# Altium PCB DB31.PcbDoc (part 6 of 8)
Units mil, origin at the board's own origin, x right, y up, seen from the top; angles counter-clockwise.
Board outline 3236.22 x 4456.69 mil, 8 copper layers (Top Layer, MidLayer1, MidLayer2, GND-Layer5, MidLayer3, VCC, MidLayer4, Bottom Layer), stack 61.8 mil thick; 226 components, 469 nets, 1815 pads, 1562 vias.
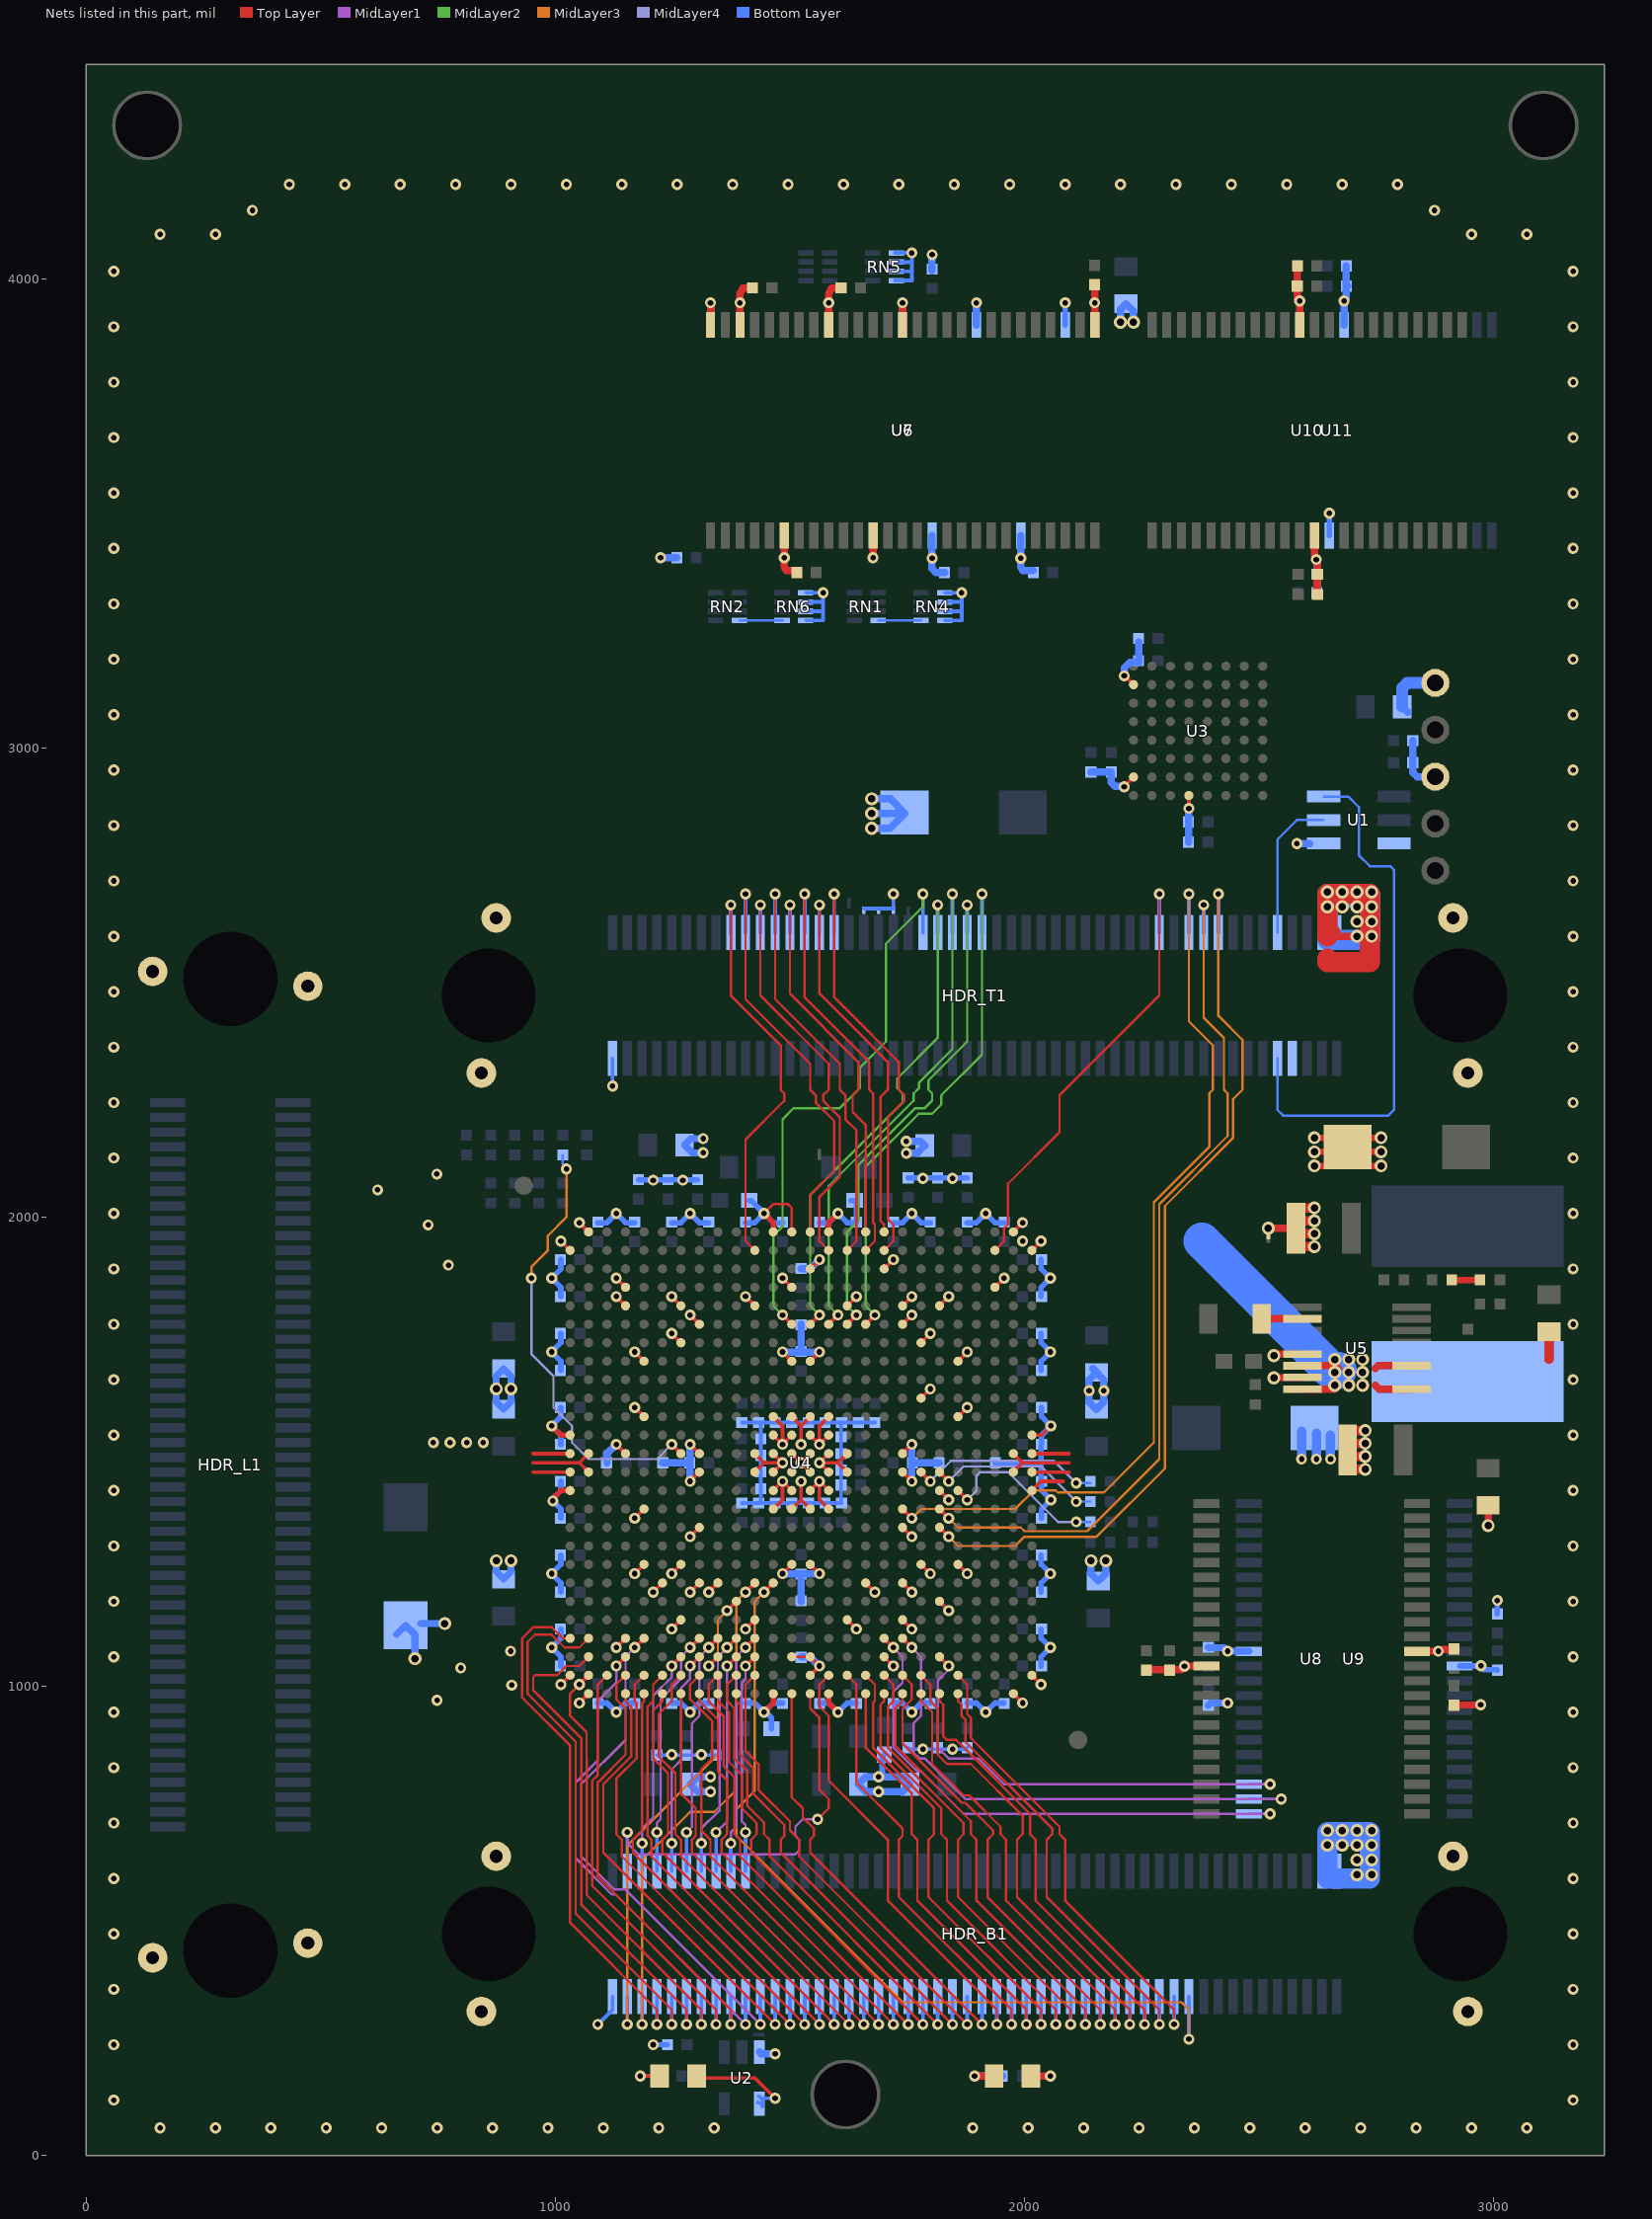
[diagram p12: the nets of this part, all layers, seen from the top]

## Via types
v1: diameter 23.62, hole 11.81, Top Layer to Bottom Layer, 947 vias
v2: diameter 23.62, hole 11.81, Top Layer to Bottom Layer, tented both sides, 476 vias
v3: diameter 27.56, hole 15.75, Top Layer to Bottom Layer, 138 vias
v4: diameter 23.62, hole 11.81, Top Layer to Bottom Layer, tented top, 1 vias

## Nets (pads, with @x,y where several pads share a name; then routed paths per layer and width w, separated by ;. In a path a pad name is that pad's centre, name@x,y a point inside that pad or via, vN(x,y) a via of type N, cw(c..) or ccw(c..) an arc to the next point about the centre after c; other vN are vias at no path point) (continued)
GND: C1.1 C2.2 C3.2 C4.2 C5.2 C6.2 C7.2 C8.2 C9.2 C10.2 C11.2 C12.2 C13.2 C14.2 C15.2 C16.2 C17.2 C18.2 C19.2 C20.2 C21.2 C22.2 C23.2 C24.2 C25.2 C26.2 C27.2 C28.2 C29.2 C30.2 C31.2 C32.2 C33.2 C34.2 C35.2 C36.2 C37.2 C38.2 C39.2 C40.2 C41.2 C42.2 C43.2 C44.2 C45.2 C46.2 C47.2 C48.2 C49.2 C50.2 C51.2 C52.2 C53.2 C54.2 C55.2 C56.2 C57.2 C58.2 C59.2 C60.2 C61.2 C62.2 C63.2 C64.2 C65.2 C66.2 C67.2 C68.2 C69.2 C70.2 C71.2 C72.2 C73.2 C74.2 C75.2 C76.2 C77.2 C78.2 C79.2 C80.2 C81.2 C82.2 C83.2 C84.2 C85.2 C86.2 C87.2 C88.2 C89.2 C90.2 C91.2 C92.2 C93.2 C94.2 C95.2 C96.2 C97.2 C98.2 C99.2 C100.2 C101.1 C102.2 C103.2 C104.2 C105.2 C106.2 C107.2 C108.2 C109.2 C110.2 C111.2 C112.2 C113.2 C114.2 C115.2 C116.2 C117.2 C118.2 C119.2 C120.2 C121.2 C122.2 C123.2 C124.2 C125.2 C128.2 C129.2 C130.2 C131.2 C132.2 C134.2 C135.2 C136.2 C137.2 C138.2 C139.2 C140.2 C141.2 C142.2 C143.2 C144.2 C145.2 C146.2 C147.2 C148.2 C149.2 C150.2 C151.2 C152.2 C153.2 C154.2 C155.2 C156.2 C157.2 HDR_B1.1 HDR_B1.98 HDR_B1.100 HDR_B1.MH1 HDR_B1.MH2 HDR_B1.MH3 HDR_B1.MH4 HDR_L1.MH1 HDR_L1.MH2 HDR_L1.MH3 HDR_L1.MH4 HDR_T1.1 HDR_T1.98 HDR_T1.100 HDR_T1.MH1 HDR_T1.MH2 HDR_T1.MH3 HDR_T1.MH4 LED2.2 NT5.2 NT6.2 NT7.2 NT8.2 RN4.1 RN4.2 RN4.3 RN4.4 RN5.1 RN5.2 RN5.3 RN5.4 RN6.1 RN6.2 RN6.3 RN6.4 TP1.1 TP3.1 U1.1 U2.3 U3.E8 U3.H2 U3.H7 U4.A2 U4.A12 U4.A13 U4.A15 U4.A25 U4.AA21 U4.AB7 U4.AB11 U4.AB16 U4.AB19 U4.AC4 U4.AD9 U4.AD13 U4.AD14 U4.AD18 U4.AE1 U4.AE14 U4.AE26 U4.AF2 U4.AF12 U4.AF15 U4.AF25 U4.B1 U4.B26 U4.C14 U4.C18 U4.D4 U4.D13 U4.D24 U4.E4 U4.E7 U4.E11 U4.E16 U4.E19 U4.E21 U4.F8 U4.F19 U4.G7 U4.G20 U4.H5 U4.H13 U4.H14 U4.H22 U4.K20 U4.L5 U4.L12 U4.L13 U4.L14 U4.L15 U4.L22 U4.M1 U4.M12 U4.M13 U4.M14 U4.M15 U4.M26 U4.N1 U4.N2 U4.N4 U4.N8 U4.N11 U4.N12 U4.N13 U4.N14 U4.N15 U4.N16 U4.N19 U4.N25 U4.N26 U4.P1 U4.P2 U4.P8 U4.P11 U4.P12 U4.P13 U4.P14 U4.P15 U4.P16 U4.P19 U4.P25 U4.P26 U4.R1 U4.R12 U4.R13 U4.R14 U4.R15 U4.R21 U4.R26 U4.T5 U4.T12 U4.T13 U4.T14 U4.T15 U4.U8 U4.U19 U4.W5 U4.W7 U4.W13 U4.W14 U4.W20 U4.W22 U4.Y6 U4.Y8 U4.Y9 U4.Y17 U4.Y19 U5.13 U5.15 U6.6 U6.12 U6.28 U6.41 U6.46 U6.52 U6.54 U7.6 U7.12 U7.28 U7.41 U7.46 U7.52 U7.54 U8.12 U8.34 U9.12 U9.34 U10.12 U10.34 U11.12 U11.34 | length 16400.1
  Top Layer w5: v1(1444.88,2007.87) 1464.57,2027.56 1496.06,2027.56 1503.94,2019.68 U4.A13@1503.94,1968.5 ; U4.AD13@1503.94,1062.99 U4.AD14@1543.31,1062.99
  Top Layer w7.87: 952.76,1456.69 U4.P1@1031.5,1456.69 ; 952.76,1476.38 1011.81,1476.38 1051.18,1476.38 ; 952.76,1496.06 U4.N1@1031.5,1496.06 ; v1(1011.81,1003.93) U4.AE1@1031.5,1023.62 ; v1(1011.81,1948.82) U4.B1@1031.5,1929.13 ; v1(1051.18,964.56) U4.AF2@1070.87,984.25 ; v1(1051.18,1988.19) U4.A2@1070.87,1968.5 ; U4.P2@1070.87,1456.69 1051.18,1476.38 ; U4.N2@1070.87,1496.06 1051.18,1476.38 ; v1(1129.92,1082.67) U4.AC4@1149.61,1102.36 ; v1(1129.92,1515.75) U4.N4@1149.61,1496.06 ; v1(1129.92,1830.71) U4.E4@1149.61,1811.02 ; v1(1129.92,1870.08) U4.D4@1149.61,1850.39 ; v1(1169.29,1240.16) U4.W5@1188.98,1259.84 ; v1(1169.29,1358.27) U4.T5@1188.98,1377.95 ; v1(1169.29,1594.49) U4.L5@1188.98,1574.8 ; v1(1169.29,1712.6) U4.H5@1188.98,1692.91 ; v1(1208.66,1200.78) U4.Y6@1228.35,1220.47 ; v1(1248.03,1122.04) U4.AB7@1267.72,1141.73 ; v1(1248.03,1240.16) U4.W7@1267.72,1259.84 ; v1(1248.03,1751.97) U4.G7@1267.72,1732.28 ; v1(1248.03,1830.71) U4.E7@1267.72,1811.02 ; v1(1287.4,1200.78) U4.Y8@1307.09,1220.47 ; v1(1287.4,1318.9) U4.U8@1307.09,1338.58 ; v1(1287.4,1437.01) U4.P8@1307.09,1456.69 ; v1(1287.4,1515.75) U4.N8@1307.09,1496.06 ; v1(1287.4,1791.34) U4.F8@1307.09,1771.65 ; v1(1326.77,1043.3) U4.AD9@1346.46,1062.99 ; v1(1326.77,1200.78) U4.Y9@1346.46,1220.47 ; v1(1405.51,1122.04) U4.AB11@1425.2,1141.73 ; v1(1405.51,1830.71) U4.E11@1425.2,1811.02 ; U4.P11@1425.2,1456.69 1444.88,1476.38 ; U4.N11@1425.2,1496.06 1444.88,1476.38 ; U4.T12@1464.57,1377.95 1484.25,1397.64 v1(1484.25,1437.01) ; U4.R12@1464.57,1417.32 v1(1484.25,1437.01) ; U4.P12@1464.57,1456.69 v1(1484.25,1476.38) ; U4.N12@1464.57,1496.06 v1(1484.25,1476.38) ; U4.M12@1464.57,1535.43 v1(1484.25,1515.75) ; U4.L12@1464.57,1574.8 1484.25,1555.12 v1(1484.25,1515.75) ; v1(1484.25,1240.15) U4.W13@1503.94,1259.84 ; v1(1484.25,1712.6) U4.H13@1503.94,1692.91 ; v1(1484.25,1870.08) U4.D13@1503.94,1850.39 ; U4.T13@1503.94,1377.95 1523.62,1397.64 ; U4.R13@1503.94,1417.32 v1(1484.25,1437.01) ; U4.P13@1503.94,1456.69 v1(1523.62,1476.38) ; U4.N13@1503.94,1496.06 v1(1523.62,1476.38) ; U4.M13@1503.94,1535.43 v1(1484.25,1515.75) ; U4.L13@1503.94,1574.8 1523.62,1555.12 ; v1(1523.62,1437.01) 1523.62,1397.64 ; v1(1523.62,1515.75) 1523.62,1555.12 ; U4.AE14@1543.31,1023.62 v1(1562.99,1043.3) U4.AD14@1543.31,1062.99 ; U4.W14@1543.31,1259.84 v1(1562.99,1240.16) ; U4.T14@1543.31,1377.95 1523.62,1397.64 ; U4.R14@1543.31,1417.32 v1(1562.99,1437.01) ; U4.P14@1543.31,1456.69 v1(1523.62,1476.38) ; U4.N14@1543.31,1496.06 v1(1523.62,1476.38) ; U4.M14@1543.31,1535.43 v1(1562.99,1515.75) ; U4.L14@1543.31,1574.8 1523.62,1555.12 ; U4.H14@1543.31,1692.91 v1(1562.99,1712.6) ; U4.C14@1543.31,1889.76 v1(1562.99,1909.45) ; U4.T15@1582.68,1377.95 1562.99,1397.64 v1(1562.99,1437.01) ; U4.R15@1582.68,1417.32 v1(1562.99,1437.01) ; U4.P15@1582.68,1456.69 v1(1562.99,1476.38) ; U4.N15@1582.68,1496.06 v1(1562.99,1476.38) ; U4.M15@1582.68,1535.43 v1(1562.99,1515.75) ; U4.L15@1582.68,1574.8 1562.99,1555.12 v1(1562.99,1515.75) ; U4.AB16@1622.05,1141.73 v1(1641.73,1122.04) ; U4.P16@1622.05,1456.69 1602.36,1476.38 ; U4.N16@1622.05,1496.06 1602.36,1476.38 ; U4.E16@1622.05,1811.02 v1(1641.73,1830.71) ; U4.Y17@1661.42,1220.47 v1(1681.1,1200.78) ; U4.AD18@1700.79,1062.99 v1(1720.47,1043.3) ; U4.C18@1700.79,1889.76 v1(1720.47,1909.45) ; U4.AB19@1740.16,1141.73 v1(1759.84,1122.04) ; U4.Y19@1740.16,1220.47 v1(1759.84,1200.78) ; U4.U19@1740.16,1338.58 v1(1759.84,1318.9) ; U4.P19@1740.16,1456.69 v1(1759.84,1437.01) ; U4.N19@1740.16,1496.06 v1(1759.84,1515.75) ; U4.F19@1740.16,1771.65 v1(1759.84,1791.34) ; U4.E19@1740.16,1811.02 v1(1759.84,1830.71) ; U4.W20@1779.53,1259.84 v1(1799.22,1240.16) ; U4.K20@1779.53,1614.17 v1(1799.22,1633.86) ; U4.G20@1779.53,1732.28 v1(1799.21,1751.97) ; U4.AA21@1818.9,1181.1 v1(1838.59,1161.41) ; U4.R21@1818.9,1417.32 v1(1838.59,1397.64) ; U4.E21@1818.9,1811.02 v1(1838.58,1830.71) ; U4.W22@1858.27,1259.84 v1(1877.96,1240.16) ; U4.L22@1858.27,1574.8 v1(1877.96,1594.49) ; U4.H22@1858.27,1692.91 v1(1877.96,1712.6) ; U4.D24@1937.01,1850.39 v1(1956.7,1870.08) ; U4.AF25@1976.38,984.25 v1(1996.07,964.57) ; U4.P25@1976.38,1456.69 1996.06,1476.38 ; U4.N25@1976.38,1496.06 1996.06,1476.38 ; U4.A25@1976.38,1968.5 v1(1996.06,1988.19) ; U4.AE26@2015.75,1023.62 v1(2035.44,1003.94) ; U4.R26@2015.75,1417.32 2035.43,1437.01 2082.68,1437.01 ; U4.P26@2015.75,1456.69 2094.49,1456.69 ; U4.N26@2015.75,1496.06 2094.49,1496.06 ; U4.M26@2015.75,1535.43 2036.42,1535.43 v1(2056.1,1555.11) ; U4.B26@2015.75,1929.13 v1(2035.43,1948.82) ; 2094.49,1476.38 1996.06,1476.38 ; v1@2212.6,2918.31 U3.H7@2232.28,2937.99 ; v1@2212.6,3154.53 U3.H2@2232.28,3134.84 ; v1(2350.4,2871.07) U3.E8@2350.39,2898.62 ; 1444.88,1476.38 v1(1484.25,1476.38) ; v1(1562.99,1476.38) 1602.36,1476.38
  Top Layer w11.81: v1@992.13,1397.64 1011.81,1417.32 U4.R1@1031.5,1417.32 ; v1(992.13,1555.12) 1011.81,1535.43 U4.M1@1031.5,1535.43 ; v1(1444.88,944.88) 1464.57,964.57 U4.AF12@1464.57,984.25 ; v1(1444.88,2007.87) 1464.57,1988.19 U4.A12@1464.57,1968.5 ; U4.AF15@1582.68,984.25 1582.68,964.57 v1(1602.36,944.88) ; U4.A15@1582.68,1968.5 1582.68,1988.19 v1(1602.36,2007.87)
  Top Layer w13.78: v3(2618.11,2109.29) C128.2@2669.08,2109.29 ; v3(2618.11,2139.29) C128.2@2669.08,2139.29 ; v3(2618.11,2169.29) C128.2@2669.08,2169.29 ; C128.2@2709.01,2109.29 v3(2759.99,2109.29) ; C128.2@2709.01,2139.29 v3(2759.99,2139.29) ; C128.2@2709.01,2169.29 v3(2759.99,2169.29)
  Top Layer w15: C145.2@2259.84,1034.45 2260.82,1035.43 2334.65,1035.43 2341,1041.79 v1(2341,1043) 2341.3,1043.3 U8.34@2387.89,1043.3 ; v3(2531.5,1657.48) 2532.26,1658.25 U5.15@2591.08,1658.25 ; v3(2531.5,1704.72) 2535.43,1708.66 U5.13@2590.55,1708.66 ; U8.12@2836.71,1074.8 2881.8,1074.8 v1(2882,1075) 2886.02,1075 2889.76,1078.74 2914.47,1078.74 C142.2@2915.44,1079.71 ; C144.2@2915.3,957.92 2917.32,957.76 2914.45,960.63 v1(2972.44,960.63)
  Top Layer w15.75: U6.54@1330.71,3901.57 v2(1330.71,3948.82) ; U6.52@1393.7,3901.57 v2(1393.7,3948.82) ; v2@1393.7,3944.88 1393.7,3964.57 ; 1393.7,3968.51 1399.61,3980.32 C138.2@1420.27,3980.31 ; C138.2@1416.34,3980.32 C138.2@1418.31,3978.34 ; U6.6@1488.19,3452.76 1488.19,3409.45 v2(1488.19,3405.51) 1488.19,3385.83 1492.13,3377.95 C135.2@1514.77,3377.95 ; U6.46@1582.68,3901.57 v2(1582.68,3948.82) ; v2@1582.68,3944.88 1582.68,3964.57 1582.68,3968.51 1588.58,3980.32 C139.2@1609.25,3980.31 ; v2(1677.17,3405.51) U6.12@1677.17,3452.76 ; U6.41@1740.16,3901.57 v2(1740.16,3948.82) ; LED2.2@2011.81,169.29 v1(2055.12,169.29) ; U6.28@2149.61,3901.57 C134.2@2149.6,3987.2 ; v3(2519.68,1976.38) C132.2@2582.67,1976.38 ; C151.2@2580.43,4028.54 C151.2@2580.57,4028.67 ; C151.2@2581.69,4027.55 2581.69,3957.68 v2(2586.61,3952.76) U10.34@2586.61,3901.57 ; U10.12@2618.11,3452.76 2618.11,3405.51 2624.72,3398.9 C154.2@2624.72,3370.07 C154.2@2625.71,3371.06 ; C150.2@2623.74,3329.72 2623.74,3370.07 C154.2@2623.77,3370.23 ; 2645.67,2598.43 v3(2708.66,2598.43) ; v3(2988.19,1342.52) C129.2@2988.18,1385.82
  Top Layer w19.68: 2645.67,2551.18 2649.61,2555.12 ; 3118.09,1696.83 C131.2@3118.1,1755.9
  Top Layer w20: C132.2@2578.73,1937 v3(2618.1,1937) ; C132.2@2578.73,1964.56 v3(2618.1,1964.56) ; C132.2@2578.73,1992.12 v3(2618.1,1992.12) ; C132.2@2578.73,2019.68 v3(2618.1,2019.68) ; C130.2@2687.01,1462.59 v3(2726.38,1462.59) ; C130.2@2687.01,1490.15 v3(2726.38,1490.15) ; C130.2@2687.01,1517.71 v3(2726.38,1517.71) ; C130.2@2687.01,1545.27 v3(2726.38,1545.27)
  Top Layer w39.37: 2645.67,2606.3 2653.54,2606.3
  Top Layer w43.31: 2645.67,2551.18 2645.67,2543.31 2736.22,2543.31 2736.22,2688.98 2645.67,2688.98 2645.67,2598.43
  Bottom Layer w7.87: v2(1090.55,279.53) 1122.05,311.02 HDR_B1.1@1122.05,338.58 ; v2(1122.05,2279.53) HDR_T1.1@1122.05,2338.58 ; C110.2@1216.53,853.34 C108.2@1342.52,853.34 ; C29.2@1397.64,1390.75 C26.2@1610.23,1390.75 ; C7.2@1397.64,1562 C11.2@1681.1,1562 ; C16.2@1437.99,1390.75 C19.2@1437.99,1527.56 C20.2@1437.99,1562 ; RN6.4@1534.64,3271.65 1570.87,3271.65 v1(1570.87,3330.71) RN6.1@1534.64,3330.71 ; RN6.3@1534.64,3291.34 1570.87,3291.34 ; RN6.2@1534.64,3311.02 1570.87,3311.02 ; C26.2@1609.25,1390.75 C10.2@1609.25,1562 ; NT7.2@1657.48,2657.48 1720.47,2657.48 v2(1720.47,2688.98) ; RN5.4@1723.62,3996.06 1759.84,3996.06 v1(1759.84,4055.12) RN5.1@1723.62,4055.12 ; RN5.3@1723.62,4015.75 1759.84,4015.75 ; RN5.2@1723.62,4035.43 1759.84,4035.43 ; C120.2@1751.97,869.09 1754.92,866.14 1875,866.14 C122.2@1877.95,869.09 ; RN4.4@1829.92,3271.65 1866.14,3271.65 v1(1866.14,3330.71) RN4.1@1829.92,3330.71 ; RN4.3@1829.92,3291.34 1866.14,3291.34 ; RN4.2@1829.92,3311.02 1866.14,3311.02
  Bottom Layer w9.84: v1(1208.66,236.22) C101.1@1239.17,236.22
  Bottom Layer w11.81: C86.2@1011.81,1043.31 1011.81,1062.99 v1(992.13,1082.68) 1011.81,1102.36 C70.2@1011.81,1122.05 ; C69.2@1011.81,1200.79 1011.81,1220.47 v1(992.13,1240.16) 1011.81,1259.84 C72.2@1011.81,1279.53 ; C74.2@1011.81,1358.27 1011.81,1377.95 992.13,1397.64 1011.81,1417.32 C93.2@1011.81,1437.01 ; C94.2@1011.81,1515.75 1011.81,1535.43 v1(992.13,1555.12) 1011.81,1574.8 C68.2@1011.81,1594.49 ; C71.2@1011.81,1673.23 1011.81,1692.91 v1(992.13,1712.6) 1011.81,1732.28 C67.2@1011.81,1751.97 ; C73.2@1011.81,1830.71 1011.81,1850.39 v1(992.13,1870.08) 1011.81,1889.76 C95.2@1011.81,1909.45 ; C85.2@1090.55,964.57 1110.24,964.57 v1(1129.92,944.88) 1149.61,964.57 C75.2@1169.29,964.57 ; C92.2@1090.55,1988.19 1110.24,1988.19 v1(1129.92,2007.87) 1149.61,1988.19 C63.2@1169.29,1988.19 ; C118.2@1177.16,2079.72 C116.2@1303.15,2079.72 ; C81.2@1248.03,964.57 1267.72,964.57 v1(1287.4,944.88) 1307.09,964.57 C80.2@1326.77,964.57 ; C66.2@1248.03,1988.19 1267.72,1988.19 v1(1287.4,2007.87) 1307.09,1988.19 C64.2@1326.77,1988.19 ; C78.2@1405.51,964.57 1425.2,964.57 v1(1444.88,944.88) ; C65.2@1405.51,1988.19 1425.2,1988.19 v1(1444.88,2007.87) ; C119.2@1413.39,2035.43 1417.33,2035.43 v1(1444.88,2007.87) ; C111.2@1460.63,909.45 1460.63,933.07 1448.82,944.88 v1(1444.88,944.88) ; C87.2@1484.25,964.57 1464.57,964.57 v1(1444.88,944.88) ; C91.2@1484.25,1988.19 1464.57,1988.19 v1(1444.88,2007.87) ; C84.2@1562.99,964.57 1582.68,964.57 v1(1602.36,944.88) 1622.05,964.57 C76.2@1641.73,964.57 ; C98.2@1562.99,1988.19 1582.68,1988.19 v1(1602.36,2007.87) 1622.05,1988.19 C59.2@1641.73,1988.19 ; C115.2@1629.92,2035.43 C115.2@1637.79,2035.43 1641.73,2031.49 C59.2@1641.73,1989.17 ; v1(1688.98,807.09) 1696.85,814.96 1696.85,850.39 C123.2@1700.78,854.33 ; C79.2@1720.47,964.57 1740.16,964.57 v1(1759.84,944.88) 1779.53,964.57 C77.2@1799.21,964.57 ; C62.2@1720.47,1988.19 1740.16,1988.19 v1(1759.84,2007.87) 1779.53,1988.19 C61.2@1799.21,1988.19 ; C112.2@1751.97,2083.66 C114.2@1877.95,2083.66 ; C82.2@1877.95,964.57 1897.64,964.57 v1(1917.32,944.88) 1937.01,964.57 C90.2@1956.7,964.57 ; C60.2@1877.95,1988.19 1897.64,1988.19 v1(1917.32,2007.87) 1937.01,1988.19 C83.2@1956.69,1988.19 ; C46.2@1937.01,1476.38 C46.2@1938,1476.38 2035.44,1476.38 ; C88.2@2035.44,1043.31 2035.44,1062.99 v1(2055.12,1082.68) 2035.44,1102.36 C52.2@2035.44,1122.05 ; C54.2@2035.44,1200.79 2035.44,1220.47 v1(2055.12,1240.16) 2035.44,1259.84 C51.2@2035.44,1279.53 ; C96.2@2035.44,1437.01 C53.2@2035.44,1515.74 ; C55.2@2035.44,1673.23 2035.44,1692.91 v1(2055.12,1712.6) 2035.44,1732.28 C56.2@2035.44,1751.97 ; C57.2@2035.44,1830.71 2035.44,1850.39 v1(2055.12,1870.08) 2035.44,1889.76 C89.2@2035.44,1909.45 ; C97.2@2036.42,1358.27 2036.42,1377.95 v1(2056.1,1397.64) 2036.42,1417.32 C96.2@2036.42,1437.01 ; C53.2@2036.41,1515.74 2036.41,1535.43 v1(2056.1,1555.11) 2036.41,1574.8 C58.2@2036.41,1594.49 ; U7.52@2086.61,3901.57 v2(2086.61,3948.82) ; U7.54@2149.61,3901.57 v2(2149.61,3948.82) ; U11.12@2649.61,3452.76 v2(2649.61,3500) ; U9.34@2927.25,1043.3 v1@2972.3,1043.3 ; v1(2973,1044) v1@2972.3,1043.3 ; C149.2@3007.87,1034.45 3006.88,1035.43 2979.33,1035.43 2972.3,1042.47 v1@2972.3,1043.3 ; C147.2@3007.87,1154.53 v1(3007.87,1183.07)
  Bottom Layer w15: C99.2@661.42,1110.59 C99.2@680.83,1130 700.79,1110.04 v3(700.79,1059.06) ; C99.2@712.6,1133.86 v3(764.13,1133.86) ; v3(874.02,1267.72) 874.02,1244.09 C38.2@889.76,1228.34 905.51,1244.09 v3(905.51,1267.72) ; v1@1314.96,2137.14 v1(1315.08,2137.24) ; v1@1315.08,2137.14 1291.99,2137.14 C35.2@1275.59,2153.54 1289.29,2167.24 v1(1315.08,2167.24) ; v2(1330.71,775.59) 1303.15,775.59 C42.2@1287.4,791.34 1303.15,807.09 v2(1330.71,807.09) ; v1@1748.03,2139.93 1748.03,2132.31 v1(1748.27,2136.26) ; v1(1748.27,2136.26) 1771.23,2136.24 C37.2@1787.52,2152.54 ; C146.2@2391.82,959.64 2396.75,964.57 v1(2433.07,964.57) ; C148.2@2391.82,1083.65 2392.8,1082.68 2425.2,1082.68 2432.87,1075 v1(2433,1075) 2433.21,1074.79 U9.12@2478.44,1074.79 ; C4.2@874.02,1606.29 874.02,1661.42 C36.2@889.76,1677.16 905.51,1661.41 905.51,1606.3 C4.2@889.76,1590.55 C4.2@874.02,1606.29 ; C5.2@1645.67,791.34 1661.42,807.09 1740.15,807.09 C41.2@1755.9,791.34 1740.16,775.59 1661.41,775.59 C5.2@1645.67,791.34
  Bottom Layer w15.75: C44.2@1110.24,1476.38 1110.24,1496.06 v1(1129.92,1515.75) ; v2(1224.41,3405.51) C136.2@1258.85,3405.51 ; C45.2@1228.35,1476.38 C32.2@1287.4,1476.38 ; v1(1287.4,1437.01) v1(1287.4,1515.75) ; U7.28@1330.71,3901.57 v2@1330.71,3944.88 ; U2.3@1435.04,220.47 1438.97,216.54 v1(1468.5,216.54) ; v1(1484.25,1240.15) v1(1562.99,1240.16) ; v1(1484.25,1712.6) v1(1562.99,1712.6) ; C48.2@1523.62,1181.1 C33.2@1523.62,1240.15 ; C49.2@1523.62,1889.76 1543.31,1889.76 v1(1562.99,1909.45) ; C43.2@1523.63,1062.99 1543.31,1062.99 v1(1562.99,1043.3) ; C31.2@1523.63,1712.6 C47.2@1523.63,1771.65 ; v3(1674.21,2828.74) 1713.39,2828.74 1745.15,2860.51 1713.93,2891.73 v3(1674.21,2891.73) ; v3(1674.21,2860.24) C100.2@1744.88,2860.24 ; U7.41@1740.16,3901.57 v2(1740.16,3948.82) ; v1(1748.03,2161.42) 1778.65,2161.42 C37.2@1787.52,2152.54 ; v1(1759.84,1437.01) C34.2@1759.85,1476.37 ; v1(1759.84,1515.75) C34.2@1759.85,1476.38 ; U7.12@1803.15,3452.76 1803.15,3405.51 v2(1803.15,3404.53) 1803.15,3381.89 1811.04,3374.01 C141.2@1829.72,3374.01 ; C137.2@1803.15,4016.72 1803.15,4047.24 v2(1803.15,4051.18) ; C50.2@1818.9,1476.38 C34.2@1759.85,1476.38 ; U7.46@1897.64,3901.57 v2(1897.64,3948.82) v2@1897.64,3944.88 ; U7.6@1992.13,3452.76 1992.13,3385.83 1996.06,3377.95 C140.2@2018.71,3377.95 ; v3(2141.73,1267.72) 2141.73,1240.15 C40.2@2157.48,1224.41 2161.42,1228.35 2173.23,1240.16 v3(2173.23,1267.72) ; C107.2@2141.73,2948.82 C104.2@2185.04,2948.82 2185.04,2926.19 2192.92,2918.31 v1@2212.6,2918.31 ; C39.2@2145.66,1677.16 2169.29,1653.54 2169.29,1606.3 C6.2@2153.54,1590.55 2137.8,1606.29 2137.8,1653.54 C39.2@2153.54,1669.29 ; v3(2204.72,3907.48) 2204.72,3935.04 C125.2@2216.53,3946.84 2232.28,3931.1 v3(2232.28,3907.48) ; v1(2212.6,3153.54) 2212.6,3170.28 2224.41,3182.09 2243.11,3182.09 C103.2@2243.11,3225.39 ; C102.2@2349.4,2799.21 2350.4,2800.2 v1(2350.4,2871.07) ; v2(2580.71,2796.26) 2608.06,2796.26 U1.1@2608.25,2796.45 ; v2(2622.05,3401.57) 2623.03,3400.6 C152.2@2623.03,3330.7 ; v2@2681.1,3956.7 v2(2681.1,3952.76) 2686.02,3957.67 C157.2@2686.02,3984.25 ; U11.34@2681.38,3901.57 v2@2681.38,3944.88 ; C153.2@2686.02,4027.55 2686.02,3987.2 C157.2@2688.98,3984.25 ; C124.2@2805.12,3087.59 C124.2@2816.93,3075.79 ; C1.1@2827.75,3015.74 C2.2@2827.75,2968.5 2827.75,2947.84 2836.92,2938.67 TP3.1@2875.71,2938.67
  Bottom Layer w20: v1(2590.55,1484.25) C3.2@2590.55,1543.31 ; v1(2622.05,1484.25) C3.2@2622.05,1539.37 ; v1(2652.34,1484.25) C3.2@2652.34,1535.44
  Bottom Layer w25: C124.2@2805.12,3087.59 2805.12,3127.96 2815.83,3138.67 TP1.1@2875.71,3138.67
  Bottom Layer w43.31: v3@2649.61,681.1 v3@2736.22,681.1 ; v3@2649.61,2681.1 v3@2736.22,2681.1 ; v3@2736.22,681.1 2736.22,688.98 2645.67,688.98 2645.67,590.55 2736.22,590.55 2736.22,598.42 2736.22,629.92 2736.22,661.42 v3@2736.22,681.1 ; v3@2736.22,2681.1 2736.22,2688.98 2645.67,2688.98 2645.67,2590.55 2736.22,2590.55 2736.22,2598.43 2736.22,2629.92 2736.22,2661.42 v3@2736.22,2681.1
  other v1: 157.48,59.06 275.59,59.06 393.7,59.06 511.81,59.06 629.92,59.06 748.03,59.06 866.14,59.06 984.25,59.06 1102.36,59.06 1220.47,59.06 1338.58,59.06 1889.76,59.06 2007.87,59.06 2125.98,59.06 2244.09,59.06 2362.2,59.06 2480.31,59.06 2598.43,59.06 2716.54,59.06 2834.65,59.06 2952.76,59.06 3070.87,59.06 59.06,118.11 3169.29,118.11 59.06,236.22 3169.29,236.22 59.06,354.33 3169.29,354.33 59.06,472.44 3169.29,472.44 59.06,590.55 3169.29,590.55 59.06,708.66 3169.29,708.66 1688.98,775.59 59.06,826.77 3169.29,826.77 1783.46,866.14 1846.46,866.14 59.06,944.88 3169.29,944.88 747.87,970.06 907.31,1002.54 798.43,1039.08 59.06,1062.99 3169.29,1062.99 904.73,1074.88 59.06,1181.1 3169.29,1181.1 59.06,1299.21 3169.29,1299.21 994.72,1395.04 59.06,1417.32 3169.29,1417.32 740.16,1519.68 775.59,1519.68 811.02,1519.68 846.46,1519.68 59.06,1535.43 3169.29,1535.43 2137.8,1629.92 2169.29,1629.92 59.06,1653.54 3169.29,1653.54 59.06,1771.65 3169.29,1771.65 59.06,1889.76 3169.29,1889.76 772.13,1897.68 1996.06,1948.82 728.95,1983.4 59.06,2007.87 3169.29,2007.87 621.27,2058.14 1208.66,2078.74 1271.65,2078.74 1783.46,2082.68 1846.46,2082.68 747.5,2091.72 59.06,2125.98 3169.29,2125.98 59.06,2244.09 3169.29,2244.09 59.06,2362.2 3169.29,2362.2 59.06,2480.31 3169.29,2480.32 59.06,2598.43 3169.29,2598.43 59.06,2716.54 3169.29,2716.54 59.06,2834.65 3169.29,2834.65 2212.6,2917.32 59.06,2952.76 3169.29,2952.76 59.06,3070.87 3169.29,3070.87 59.06,3188.98 3169.29,3188.98 59.06,3307.09 3169.29,3307.09 59.06,3425.2 3169.29,3425.2 59.06,3543.31 3169.29,3543.31 59.06,3661.42 3169.29,3661.42 59.06,3779.53 3169.29,3779.53 59.06,3897.64 3169.29,3897.64 59.06,4015.75 3169.29,4015.75 157.48,4094.49 275.59,4094.49 2952.76,4094.49 3070.87,4094.49 354.33,4145.67 2874.02,4145.67 433.07,4200.79 551.18,4200.79 669.29,4200.79 787.4,4200.79 905.51,4200.79 1023.62,4200.79 1141.73,4200.79 1259.84,4200.79 1377.95,4200.79 1496.06,4200.79 1614.17,4200.79 1732.28,4200.79 1850.39,4200.79 1968.5,4200.79 2086.61,4200.79 2204.72,4200.79 2322.83,4200.79 2440.94,4200.79 2559.06,4200.79 2677.17,4200.79 2795.28,4200.79
  other v2: 1248.03,854.33 1311.02,854.33 1992.13,3404.53
  other v3: 2708.66,598.42 2740.16,598.42 2708.66,629.92 2740.16,629.92 2645.67,661.42 2677.17,661.42 2708.66,661.42 2740.16,661.42 2645.67,692.91 2677.17,692.91 2708.66,692.91 2740.16,692.91 874.02,1633.86 905.51,1633.86 2740.16,2598.43 2708.66,2629.92 2740.16,2629.92 2645.67,2661.42 2677.17,2661.42 2708.66,2661.42 2740.16,2661.42 2645.67,2692.91 2677.17,2692.91 2708.66,2692.91 2740.16,2692.91
IO0: HDR_B1.7 U4.AC1 | length 1122.9
  Top Layer w5: U4.AC1@1031.5,1102.36 1015.75,1102.36 992.13,1125.98 968.5,1125.98 956.69,1125.98 952.76,1125.98 929.13,1102.36 929.13,976.38 1031.5,874.02 1031.5,496.06 1216.54,311.02 v2(1216.54,279.53)
  Bottom Layer w7.87: v2(1216.54,279.53) HDR_B1.7@1216.54,338.58
IO1: HDR_B1.9 U4.AC2 | length 1157.2
  Top Layer w5: U4.AC2@1070.87,1102.36 1051.18,1082.68 1019.68,1082.68 992.13,1110.24 968.5,1110.24 956.69,1110.24 940.94,1094.49 940.94,984.25 1043.31,881.89 1043.31,515.75 1248.03,311.02 v2(1248.03,279.53)
  Bottom Layer w7.87: v2(1248.03,279.53) HDR_B1.9@1248.03,338.58
IO2: HDR_B1.11 U4.AD2 | length 1070.6
  Top Layer w5: U4.AD2@1070.87,1062.99 1051.18,1043.31 1023.62,1043.31 1003.94,1023.62 968.5,1023.62 956.69,1023.62 952.76,1019.68 952.76,992.13 1055.12,889.76 1055.12,535.43 1279.53,311.02 v2(1279.53,279.53)
  Bottom Layer w7.87: v2(1279.53,279.53) HDR_B1.11@1279.53,338.58
IO3: HDR_B1.13 U4.AE2 | length 935.2
  Top Layer w5: v1(1051.18,1003.93) 1031.5,984.25 1031.5,956.69 1031.5,944.88 1031.5,937.01 1066.44,902.07 1066.44,846.95 1066.93,846.46 1066.93,555.12 1311.02,311.02 v2(1311.02,279.53)
  Top Layer w7.87: v1(1051.18,1003.93) U4.AE2@1070.87,1023.62
  Bottom Layer w7.87: v2(1311.02,279.53) HDR_B1.13@1311.03,338.58
IO4: HDR_B1.15 U4.AE3 | length 925.5
  Top Layer w5: U4.AE3@1110.24,1023.62 1090.55,1003.94 1090.55,921.26 1090.55,909.45 1090.55,811.02 1078.74,799.21 1078.74,574.8 1342.52,311.02 v2(1342.52,279.53)
  Bottom Layer w7.87: v2(1342.52,279.53) HDR_B1.15@1342.52,338.58
IO5: HDR_B1.17 U4.AE4 | length 961.3
  Top Layer w5: U4.AE4@1149.61,1023.62 1129.92,1003.94 1129.92,972.44 1149.61,952.76 1149.61,921.26 1149.61,909.45 1149.61,854.33 1090.55,795.28 1090.55,594.49 1374.02,311.02 v2(1374.02,279.53)
  Bottom Layer w7.87: v2(1374.02,279.53) HDR_B1.17@1374.02,338.58
IO6: HDR_B1.19 U4.AD4 | length 1041.2
  Top Layer w7.87: v1(1129.92,1043.3) U4.AD4@1149.61,1062.99
  MidLayer1 w5: v1(1129.92,1043.3) 1129.92,1007.87 1090.55,968.5 1090.55,921.26 1090.55,909.45 1090.55,842.52 1043.31,795.27 1043.31,633.86 1120.32,556.84 1128.2,556.84 v2(1405.51,279.53)
  Bottom Layer w7.87: v2(1405.51,279.53) HDR_B1.19@1405.51,338.58
IO7: HDR_B1.21 U4.AC5 | length 1109.4
  Top Layer w7.87: v1(1169.29,1082.67) U4.AC5@1188.98,1102.36
  MidLayer1 w5: v1(1169.29,1082.67) 1149.61,1062.99 1149.61,921.26 1149.61,909.45 1149.61,885.83 1055.12,791.34 1055.12,637.8 1125.98,566.93 1149.61,566.93 v2(1437.01,279.53)
  Bottom Layer w7.87: v2(1437.01,279.53) HDR_B1.21@1437.01,338.58
IO8: HDR_B1.23 U4.AF4 | length 944.8
  Top Layer w5: U4.AF4@1149.61,984.25 1149.61,968.51 1161.42,956.7 1161.42,921.26 1161.42,909.45 1161.42,850.39 1102.36,791.34 1102.36,645.67 v2(1468.5,279.53)
  Bottom Layer w7.87: v2(1468.5,279.53) HDR_B1.23@1468.51,338.58
IO9: HDR_B1.25 U4.AE5 | length 984.2
  Top Layer w5: U4.AE5@1188.98,1023.62 1169.29,1003.94 1169.29,968.5 1173.23,964.57 1173.23,921.26 1173.23,909.45 1173.23,846.46 1129.92,803.15 1129.92,685.04 1141.73,673.23 1141.73,637.79 v2(1500,279.53)
  Bottom Layer w7.87: v2(1500,279.53) HDR_B1.25@1500,338.58
IO10: HDR_B1.27 U4.AF5 | length 925.2
  Top Layer w5: U4.AF5@1188.98,984.25 1188.98,968.5 1185.04,964.57 1185.04,921.26 1185.04,909.45 1185.04,692.91 1165.35,673.23 1165.35,645.67 v2(1531.5,279.53)
  Bottom Layer w7.87: v2(1531.5,279.53) HDR_B1.27@1531.5,338.58
IO11: HDR_B1.29 U4.AE6 | length 967.9
  Top Layer w5: U4.AE6@1228.35,1023.62 1208.66,1003.94 1208.66,968.5 1196.85,956.69 1196.85,921.26 1196.85,909.45 1196.85,681.1 1204.72,673.23 1204.72,637.79 v2(1562.99,279.53)
  Bottom Layer w7.87: v2(1562.99,279.53) HDR_B1.29@1562.99,338.58
IO12: HDR_B1.31 U4.AF6 | length 941.5
  Top Layer w5: U4.AF6@1228.35,984.25 1228.35,968.5 1208.66,948.82 1208.66,921.26 1208.66,909.45 1208.66,846.46 1240.16,814.96 1240.16,685.04 1228.35,673.23 1228.35,645.67 v2(1594.49,279.53)
  Bottom Layer w7.87: v2(1594.49,279.53) HDR_B1.31@1594.49,338.58
IO13: HDR_B1.33 U4.AE7 | length 990.7
  Top Layer w5: U4.AE7@1267.72,1023.62 1248.03,1003.94 1248.03,968.5 1220.47,940.94 1220.47,921.26 1220.47,909.45 1220.47,850.39 1255.91,814.96 1255.91,685.04 1267.72,673.23 1267.72,637.79 v2(1625.99,279.53)
  Bottom Layer w7.87: v2(1625.99,279.53) HDR_B1.33@1625.99,338.58
IO14: HDR_B1.35 U4.AF7 | length 931.7
  Top Layer w5: U4.AF7@1267.72,984.25 1267.72,968.5 1267.72,921.26 1267.72,909.45 1267.72,771.65 1299.21,740.16 1299.21,681.1 1291.34,673.23 1291.34,645.67 v2(1657.48,279.53)
  Bottom Layer w7.87: v2(1657.48,279.53) HDR_B1.35@1657.48,338.58
IO15: HDR_B1.37 U4.AE8 | length 997.2
  Top Layer w5: U4.AE8@1307.09,1023.62 1287.4,1003.94 1287.4,972.44 1334.65,925.2 1334.65,921.26 1334.65,909.45 1334.65,846.46 1311.02,822.83 1311.02,692.91 1330.71,673.23 1330.71,637.79 v2(1688.98,279.53)
  Bottom Layer w7.87: v2(1688.98,279.53) HDR_B1.37@1688.98,338.58
IO16: HDR_B1.39 U4.AF8 | length 944.8
  Top Layer w5: U4.AF8@1307.09,984.25 1307.09,968.51 1346.46,929.14 1346.46,921.26 1346.46,909.45 1346.46,818.9 1366.14,799.21 1366.14,685.04 1354.33,673.23 1354.33,645.67 v2(1720.47,279.53)
  Bottom Layer w7.87: v2(1720.47,279.53) HDR_B1.39@1720.48,338.58
IO17: HDR_B1.41 U4.AE9 | length 987.4
  Top Layer w5: U4.AE9@1346.46,1023.62 1326.77,1003.94 1326.77,968.5 1358.27,937.01 1358.27,921.26 1358.27,909.45 1358.27,830.46 1381.89,806.84 1381.89,685.04 1393.7,673.23 1393.7,637.79 v2(1751.97,279.53)
  Bottom Layer w7.87: v2(1751.97,279.53) HDR_B1.41@1751.97,338.58
IO18: HDR_B1.43 U4.AF9 | length 954.6
  Top Layer w5: U4.AF9@1346.46,984.25 1346.46,968.5 1370.08,944.88 1370.08,921.26 1370.08,909.45 1370.08,838.58 1397.64,811.02 1397.64,740.16 1429.13,708.66 1429.13,685.04 1417.32,673.23 1417.32,645.67 v2(1783.47,279.53)
  Bottom Layer w7.87: v2(1783.47,279.53) HDR_B1.43@1783.47,338.58
IO19: HDR_B1.45 U4.AE10 | length 997.2
  Top Layer w5: U4.AE10@1385.83,1023.62 1366.14,1003.94 1366.14,968.5 1381.89,952.76 1381.89,921.26 1381.89,909.45 1381.89,846.46 1409.45,818.9 1409.45,745.08 1444.88,709.64 1444.88,685.04 1456.69,673.23 1456.69,637.79 v2(1814.96,279.53)
  Bottom Layer w7.87: v2(1814.96,279.53) HDR_B1.45@1814.96,338.58
IO20: HDR_B1.47 U4.AF10 | length 961.1
  Top Layer w5: U4.AF10@1385.83,984.25 1385.83,968.5 1393.7,960.63 1393.7,921.26 1393.7,909.45 1393.7,854.33 1421.26,826.77 1421.26,771.65 1488.19,704.72 1488.19,681.1 1480.31,673.23 1480.31,645.67 v2(1846.46,279.53)
  Bottom Layer w7.87: v2(1846.46,279.53) HDR_B1.47@1846.46,338.58
IO21: HDR_B1.49 U4.AE11 | length 1007
  Top Layer w5: U4.AE11@1425.2,1023.62 1405.51,1003.93 1405.51,921.26 1405.51,909.45 1405.51,862.2 1433.07,834.65 1433.07,779.53 1500,712.6 1500,692.91 1519.69,673.23 1519.69,637.79 v2(1877.95,279.53)
  Bottom Layer w7.87: v2(1877.95,279.53) HDR_B1.49@1877.96,338.58
IO22: HDR_B1.51 U4.AF13 | length 938.3
  Top Layer w5: U4.AF13@1503.94,984.25 1503.94,921.26 1503.94,909.45 1503.94,763.78 1527.56,740.16 1527.56,720.47 1551.18,696.85 1551.18,681.1 1543.31,673.23 1543.31,645.67 v2(1909.45,279.53)
  Bottom Layer w7.87: v2(1909.45,279.53) HDR_B1.51@1909.45,338.58
IO23: HDR_B1.53 U4.AE15 | length 967.9
  Top Layer w5: U4.AE15@1582.68,1023.62 1562.99,1003.93 1562.99,956.69 1582.68,937.01 1582.68,921.26 1582.68,909.45 1582.68,799.21 1708.66,673.23 1708.66,543.31 1940.95,311.02 v2(1940.95,279.53)
  Bottom Layer w7.87: v2(1940.95,279.53) HDR_B1.53@1940.95,338.58
IO24: HDR_B1.55 U4.AE16 | length 954.8
  Top Layer w5: U4.AE16@1622.05,1023.62 1641.73,1003.93 1641.73,921.26 1641.73,909.45 1641.73,795.28 1740.16,696.85 1740.16,681.1 1732.28,673.23 1732.28,551.18 1972.44,311.02 v2(1972.44,279.53)
  Bottom Layer w7.87: v2(1972.44,279.53) HDR_B1.55@1972.44,338.58
IO25: HDR_B1.57 U4.AF17 | length 905.7
  Top Layer w5: U4.AF17@1661.42,984.25 1661.42,921.26 1661.42,909.45 1661.42,870.08 1759.84,771.65 1759.84,685.04 1771.65,673.23 1771.65,543.31 2003.94,311.02 v2(2003.94,279.53)
  Bottom Layer w7.87: v2(2003.94,279.53) HDR_B1.57@2003.94,338.58
IO26: HDR_B1.59 U4.AE17 | length 971.1
  Top Layer w5: U4.AE17@1661.42,1023.62 1681.1,1003.94 1681.1,968.5 1677.17,964.57 1677.17,921.26 1677.17,909.45 1677.17,870.08 1807.09,740.16 1807.09,685.04 1795.27,673.23 1795.27,551.18 2035.43,311.02 v2(2035.43,279.53)
  Bottom Layer w7.87: v2(2035.43,279.53) HDR_B1.59@2035.44,338.58
IO27: HDR_B1.61 U4.AF18 | length 922
  Top Layer w5: U4.AF18@1700.79,984.25 1700.79,968.5 1692.91,960.63 1692.91,921.26 1692.91,909.45 1692.91,870.08 1822.83,740.16 1822.83,685.04 1834.64,673.23 1834.64,543.31 2066.93,311.02 v2(2066.93,279.53)
  Bottom Layer w7.87: v2(2066.93,279.53) HDR_B1.61@2066.93,338.58
IO28: HDR_B1.63 U4.AE18 | length 987.4
  Top Layer w5: U4.AE18@1700.79,1023.62 1720.47,1003.94 1720.47,968.5 1708.66,956.69 1708.66,921.26 1708.66,909.45 1708.66,870.08 1870.08,708.66 1870.08,685.04 1858.27,673.23 1858.27,551.18 2098.43,311.02 v2(2098.43,279.53)
  Bottom Layer w7.87: v2(2098.43,279.53) HDR_B1.63@2098.43,338.58
IO29: HDR_B1.65 U4.AF19 | length 938.3
  Top Layer w5: U4.AF19@1740.16,984.25 1740.16,968.51 1724.41,952.76 1724.41,921.26 1724.41,909.45 1724.41,874.02 1885.83,712.6 1885.83,685.04 1897.64,673.23 1897.64,543.31 2129.92,311.02 v2(2129.92,279.53)
  Bottom Layer w7.87: v2(2129.92,279.53) HDR_B1.65@2129.92,338.58
IO30: HDR_B1.67 U4.AE19 | length 1008.3
  Top Layer w5: U4.AE19@1740.16,1023.62 1759.84,1003.94 1759.84,972.44 1740.16,952.76 1740.16,921.26 1740.16,909.45 1740.16,877.95 1866.14,751.97 1874.02,751.97 1933.07,692.91 1933.07,685.04 1921.26,673.23 1921.26,551.18 2161.42,311.02 v2(2161.42,279.53)
  Bottom Layer w7.87: v2(2161.42,279.53) HDR_B1.67@2161.42,338.58
IO31: HDR_B1.69 U4.AF20 | length 941.9
  Top Layer w5: U4.AF20@1779.53,984.25 1779.53,968.5 1803.15,944.88 1803.15,921.26 1803.15,909.45 1803.15,834.65 1870.08,767.72 1881.89,767.72 1948.82,700.79 1948.82,685.04 1960.63,673.23 1960.63,543.31 2192.91,311.02 v2(2192.91,279.53)
  Bottom Layer w7.87: v2(2192.91,279.53) HDR_B1.69@2192.92,338.58
IO32: HDR_B1.71 U4.AE20 | length 1027.2
  Top Layer w5: U4.AE20@1779.53,1023.62 1799.21,1003.94 1799.21,968.5 1814.96,952.75 1814.96,921.26 1814.96,909.45 1814.96,854.33 1834.65,834.65 1885.83,834.65 1996.06,724.41 1996.06,685.04 1984.25,673.23 1984.25,551.18 2224.41,311.02 v2(2224.41,279.53)
  Bottom Layer w7.87: v2(2224.41,279.53) HDR_B1.71@2224.41,338.58
IO33: HDR_B1.73 U4.AF21 | length 956.3
  Top Layer w5: U4.AF21@1818.9,984.25 1818.9,968.5 1826.77,960.63 1826.77,921.26 1826.77,909.45 1826.77,893.7 1834.65,885.83 1854.33,885.83 1866.14,874.02 2011.81,728.35 2011.81,685.04 2023.62,673.23 2023.62,543.31 2255.91,311.02 v2(2255.91,279.53)
  Bottom Layer w7.87: v2(2255.91,279.53) HDR_B1.73@2255.91,338.58
IO34: HDR_B1.75 U4.AF22 | length 951.3
  Top Layer w5: U4.AF22@1858.27,984.25 1858.27,968.5 1866.14,960.63 1866.14,937.01 1874.02,929.13 1874.02,921.26 1874.02,909.45 1874.02,881.89 2059.05,696.85 2059.05,685.04 2047.24,673.23 2047.24,551.18 2287.4,311.02 v2(2287.4,279.53)
  Bottom Layer w7.87: v2(2287.4,279.53) HDR_B1.75@2287.41,338.58
IO35: HDR_B1.77 U4.AE22 | length 994
  Top Layer w5: U4.AE22@1858.27,1023.62 1877.95,1003.94 1877.95,940.95 1885.83,933.07 1885.83,921.26 1885.83,909.45 1885.83,889.76 2074.8,700.79 2074.8,685.04 2086.61,673.23 2086.61,543.31 2318.9,311.02 v2(2318.9,279.53)
  Bottom Layer w7.87: v2(2318.9,279.53) HDR_B1.77@2318.9,338.58
KBCLOCK: HDR_T1.26 U4.A17 | length 832.6
  Top Layer w5: v2(1500,2665.35) 1500,2476.38 1645.67,2330.71 1645.67,2271.65 1633.86,2259.84 1633.86,2224.41 1661.42,2196.85 1661.42,2039.37 1661.42,2031.5 U4.A17@1661.42,1968.5
  Bottom Layer w7.87: HDR_T1.26@1500,2606.3 v2(1500,2665.35)
KBDATA: HDR_T1.28 U4.B17 | length 912.6
  Top Layer w5: v2(1531.5,2688.98) 1531.5,2515.75 1531.5,2468.5 1669.29,2330.71 1669.29,2271.65 1677.17,2263.78 1677.17,2039.37 1677.17,2031.5 1677.17,1988.19 1681.1,1984.25 1681.1,1948.82 U4.B17@1661.42,1929.13
  Bottom Layer w7.87: HDR_T1.28@1531.5,2606.3 v2(1531.5,2688.98)
LED0: HDR_B1.6 U4.AD7 | length 490.9
  Top Layer w7.87: v1(1248.03,1043.3) U4.AD7@1267.72,1062.99
  MidLayer1 w5: v2(1185.04,665.35) 1185.04,696.85 1208.66,720.47 1208.66,909.45 1208.66,921.26 1208.66,980.31 1248.03,1019.68 v1(1248.03,1043.3)
  Bottom Layer w7.87: HDR_B1.6@1185.04,606.3 v2(1185.04,665.35)
LED1: HDR_B1.8 U4.AC8 | length 533.6
  Top Layer w7.87: v1(1287.4,1082.67) U4.AC8@1307.09,1102.36
  MidLayer1 w5: v2(1216.54,688.98) 1216.54,708.66 1224.41,716.54 1224.41,909.45 1224.41,921.26 1224.41,972.44 1267.72,1015.75 1267.72,1062.99 v1(1287.4,1082.67)
  Bottom Layer w7.87: HDR_B1.8@1216.54,606.3 v2(1216.54,688.98)
LED2: HDR_B1.10 U4.AD8 | length 481.2
  Top Layer w7.87: v1(1287.4,1043.3) U4.AD8@1307.09,1062.99
  MidLayer1 w5: v2(1248.03,665.35) 1248.03,822.83 1267.72,842.52 1267.72,909.45 1267.72,921.26 1267.72,996.06 1287.4,1015.74 v1(1287.4,1043.3)
  Bottom Layer w7.87: HDR_B1.10@1248.03,606.3 v2(1248.03,665.35)
LED3: HDR_B1.12 U4.AC9 | length 523.8
  Top Layer w7.87: v1(1326.77,1082.67) U4.AC9@1346.46,1102.36
  MidLayer1 w5: v2(1279.53,688.98) 1291.34,700.79 1291.34,909.45 1291.34,921.26 1307.09,937.01 1307.09,1062.99 v1(1326.77,1082.67)
  Bottom Layer w7.87: HDR_B1.12@1279.53,606.3 v2(1279.53,688.98)
LED4: HDR_B1.14 U4.AC10 | length 530.3
  Top Layer w7.87: v1(1366.14,1082.67) U4.AC10@1385.83,1102.36
  MidLayer1 w5: v2(1311.02,665.35) 1311.02,696.85 1350.39,736.22 1350.39,909.45 1350.39,921.26 1350.39,1023.62 1346.46,1027.56 1346.46,1062.99 v1(1366.14,1082.67)
  Bottom Layer w7.87: HDR_B1.14@1311.03,606.3 v2(1311.02,665.35)
LED5: HDR_B1.16 U4.AD10 | length 474.6
  Top Layer w7.87: v1(1366.14,1043.3) U4.AD10@1385.83,1062.99
  MidLayer1 w5: v2(1342.52,688.98) 1366.14,712.6 1366.14,909.45 1366.14,921.26 v1(1366.14,1043.3)
  Bottom Layer w7.87: HDR_B1.16@1342.52,606.3 v2(1342.52,688.98)
LED6: HDR_B1.18 U4.AC11 | length 517.3
  Top Layer w7.87: v1(1405.51,1082.67) U4.AC11@1425.2,1102.36
  MidLayer1 w5: v2(1374.02,665.35) 1374.02,688.98 1385.83,700.79 1385.83,909.45 1385.83,921.26 1385.83,1062.99 v1(1405.51,1082.67)
  Bottom Layer w7.87: HDR_B1.18@1374.02,606.3 v2(1374.02,665.35)
LED7: HDR_B1.20 U4.AD11 | length 471.4
  Top Layer w7.87: v1(1405.51,1043.3) U4.AD11@1425.2,1062.99
  MidLayer1 w5: v2(1405.51,688.98) 1405.51,704.72 1397.64,712.6 1397.64,909.45 1397.64,921.26 1397.64,1007.87 1405.51,1015.75 v1(1405.51,1043.3)
  Bottom Layer w7.87: HDR_B1.20@1405.51,606.3 v2(1405.51,688.98)
LED_PGM: LED1.2 U2.4 | length 255.9
  Top Layer w7.87: LED1.2@1295.28,165.35 1301.18,165.35 1425.2,165.35 v1(1468.5,122.05)
  Bottom Layer w7.87: U2.4@1431.51,112.95 1435.5,111.55 U2.4@1440.94,109.65 ; U2.4@1433.07,125.98 1435.04,125.98 1438.97,122.05 v1(1468.5,122.05) ; U2.4@1440.94,104.33 U2.4@1440.94,109.65 ; U2.4@1440.94,122.05 1440.94,110.24 U2.4@1440.94,109.65
LED_PWR: LED2.1 R2.2 | length 102.8
  Top Layer w15.75: v1(1893.7,169.29) LED2.1@1935.04,169.29 LED2.1@1937.01,169.29
  Bottom Layer w15.75: v1(1893.7,169.29) R2.2@1953.23,169.29
LX: L5.1 U5.1 U5.3 U5.14 U5.16 | length 727.1
  Top Layer w15.75: U5.16@2592.58,1633.25 2660.81,1633.25 v3@2669.29,1641.73 ; U5.14@2592.58,1683.25 2651.4,1683.25 ; 2653.54,1681.1 2651.4,1683.25 ; v3@2669.29,1677.17 2663.21,1683.25 2651.4,1683.25 ; 2748.03,1641.73 2756.52,1633.25 U5.1@2824.58,1633.25 ; 2748.03,1677.17 2754.11,1683.25 U5.3@2824.58,1683.25
  Bottom Layer w78.74: 2377.95,1948.82 2653.54,1673.23 v3@2669.29,1673.23
  other v3: 2661.42,1641.73 2690.96,1641.73 2720.5,1641.73 2661.42,1669.29 2690.96,1669.29 2720.5,1669.29 2661.42,1696.85 2690.96,1696.85 2720.5,1696.85
MOUSECLOCK: HDR_T1.30 U4.A18 | length 826
  Top Layer w5: v2(1562.99,2665.35) 1562.99,2476.38 1639.78,2399.59 1708.66,2330.71 1708.66,2271.65 1692.91,2255.91 1692.91,2039.37 1692.91,2031.5 1692.91,1992.13 1700.79,1984.25 U4.A18@1700.79,1968.5
  Bottom Layer w7.87: HDR_T1.30@1562.99,2606.3 v2(1562.99,2665.35)
MOUSEDATA: HDR_T1.32 U4.B18 | length 932.2
  Top Layer w5: v2(1594.49,2688.98) 1594.49,2468.5 1619.95,2443.04 1732.28,2330.71 1732.28,2271.65 1744.09,2259.84 1744.09,2248.03 1708.66,2212.6 1708.66,2039.37 1708.66,2031.5 1708.66,1996.06 1720.47,1984.25 1720.47,1948.82 U4.B18@1700.79,1929.13
  Bottom Layer w7.87: HDR_T1.32@1594.49,2606.3 v2(1594.49,2688.98)
MSEL0: R13.2 U4.P20 | length 406.4
  Top Layer w7.87: U4.P20@1779.53,1456.69 v1(1799.22,1437.01)
  MidLayer4 w5: v1(1799.22,1437.01) 1842.52,1480.31 2062.99,1480.31 v1(2110.24,1433.07)
  Bottom Layer w5: v1(2110.24,1433.07) R13.2@2140.23,1433.07
MSEL1: R12.2 U4.P21 | length 373.5
  Top Layer w7.87: U4.P21@1818.9,1456.69 v1(1838.59,1437.01)
  MidLayer4 w5: v1(1838.59,1437.01) 1870.08,1468.5 2035.43,1468.5 v1(2110.24,1393.7)
  Bottom Layer w5: v1(2110.24,1393.7) R12.2@2140.23,1393.7
NCONFIG: R14.2 U4.N7 | length 951
  Top Layer w7.87: v1(1248.03,1515.75) U4.N7@1267.72,1496.06
  MidLayer3 w5: v1(948.82,1870.08) 948.82,1893.7 984.25,1929.13 984.25,1960.63 1023.62,2000 v1(1023.62,2102.36)
  MidLayer4 w5: v1(948.82,1870.08) 948.82,1708.66 996.06,1661.42 996.06,1594.49 1035.43,1555.12 1035.43,1519.68 1070.87,1484.25 1216.54,1484.25 v1(1248.03,1515.75)
  Bottom Layer w5: R14.2@1015.75,2132.36 1015.75,2114.18 1023.62,2106.3 v1(1023.62,2102.36)
NetLED1_1: LED1.1 R1.2 | length 87.1
  Top Layer w7.87: v1(1181.1,169.29) LED1.1@1222.44,169.29
  Bottom Layer w7.87: v1(1181.1,169.29) R1.2@1226.85,169.29
NetR21_2: R21.2 R22.1 | length 60
  Top Layer w13.78: R21.2@2910.94,1866.14 R22.1@2970.94,1866.14
NetRN1_8: RN1.8 RN4.5 | length 91.3
  Bottom Layer w5: RN1.8@1688.58,3271.65 RN4.5@1779.53,3271.65 RN4.5@1779.92,3271.65
NetRN2_8: RN2.8 RN6.5 | length 91.3
  Bottom Layer w5: RN2.8@1393.3,3271.65 RN6.5@1483.28,3271.66 RN6.5@1484.64,3271.65
NEXUS_TCK: HDR_T1.82 U4.T21 | length 1873.4
  Top Layer w7.87: U4.T21@1818.9,1377.95 v1(1838.59,1358.27)
  MidLayer3 w5: v1(1838.59,1358.27) 1858.27,1338.58 1927.17,1338.58 1992.13,1338.58 2000,1330.71 2025.59,1330.71 2078.74,1330.71 2090.55,1330.71 2133.86,1330.71 2287.4,1484.25 2287.4,2027.56 2433.07,2173.23 2433.07,2263.78 2425.2,2271.65 2425.2,2381.89 2381.89,2425.2 v2(2381.89,2665.35)
  Bottom Layer w7.87: HDR_T1.82@2381.89,2606.3 v2(2381.89,2665.35)
NEXUS_TDI: HDR_T1.84 U4.U21 | length 1961.9
  Top Layer w7.87: U4.U21@1818.9,1338.58 v1(1838.59,1318.9)
  MidLayer3 w5: v1(1838.59,1318.9) 1858.27,1299.21 1980.31,1299.21 2000,1318.9 2078.74,1318.9 2090.55,1318.9 2153.54,1318.9 2299.21,1464.57 2299.21,2023.62 2444.88,2169.29 2444.88,2251.97 2464.57,2271.65 2464.57,2377.95 2413.38,2429.13 v2(2413.38,2688.98)
  Bottom Layer w7.87: HDR_T1.84@2413.39,2606.3 v2(2413.38,2688.98)
NEXUS_TDO: HDR_T1.76 U4.B24 | length 987.7
  Top Layer w5: U4.B24@1937.01,1929.13 1956.69,1948.82 1956.69,1976.38 1964.57,1984.25 1964.57,2031.5 1964.57,2039.37 1964.57,2070.87 2074.8,2181.1 2074.8,2259.84 2086.61,2271.65 2287.4,2472.44 v2(2287.4,2688.98)
  Bottom Layer w7.87: HDR_T1.76@2287.4,2606.3 v2(2287.4,2688.98)
NEXUS_TMS: HDR_T1.80 U4.T19 | length 1939
  Top Layer w7.87: U4.T19@1740.16,1377.95 v1(1759.84,1358.27)
  MidLayer3 w5: v1@1760.03,1358.08 1779.89,1377.95 1980.31,1377.95 2019.68,1417.32 2066.93,1417.32 2070.87,1413.39 2078.74,1413.39 2090.55,1413.39 2169.29,1413.39 2275.59,1519.69 2275.59,2031.5 2393.7,2149.61 2393.7,2263.78 2401.57,2271.65 2401.57,2366.14 2350.39,2417.33 v2(2350.39,2688.98)
  Bottom Layer w7.87: HDR_T1.80@2350.4,2606.3 v2(2350.39,2688.98)
NSTATUS: R18.2 U4.R22 | length 377.1
  Top Layer w7.87: U4.R22@1858.27,1417.32 v1(1877.96,1397.64)
  MidLayer4 w5: v1(1877.96,1397.64) 1897.64,1417.32 1897.64,1448.82 1905.51,1456.69 1964.57,1456.69 2070.87,1350.39 v1(2110.24,1350.39)
  Bottom Layer w5: v1(2110.24,1350.39) R18.2@2140.23,1350.39
ONE_WIRE.PIO2: U1.6
ONE_WIRE_DB_PB: HDR_B1.79 U4.Y12 | length 1843.4
  Top Layer w7.87: v1(1444.88,1200.78) U4.Y12@1464.57,1220.47
  MidLayer3 w5: v1(1444.88,1200.78) 1425.2,1181.1 1425.2,921.26 1425.2,909.45 1425.2,777.56 1385.83,738.19 1385.83,681.1 1740.16,326.77 2334.65,326.77 2350.39,311.02 v2(2350.39,248.03)
  Bottom Layer w7.87: v2(2350.39,248.03) HDR_B1.79@2350.4,338.58
ONE_WIRE_DBID: HDR_T1.92 U1.2 | length 314.2
  Bottom Layer w5: HDR_T1.92@2539.37,2606.3 2539.37,2678.98 2539.37,2805.12 2580.71,2846.46 U1.2@2637.59,2846.45
ONE_WIRE_PIO1: HDR_T1.91 U1.3 | length 1154.4
  Bottom Layer w5: HDR_T1.91@2539.37,2338.58 2539.37,2259.84 2539.37,2228.35 2551.18,2216.54 2775.59,2216.54 2787.4,2228.35 2787.4,2740.16 2779.53,2748.03 2736.22,2748.03 2712.6,2771.65 2712.6,2874.02 2690.16,2896.45 U1.3@2637.59,2896.45
REF_1V2: C133.2 U5.10 | length 86.8
  Top Layer w15.75: C133.2@2505.9,1783.46 2506.11,1783.25 U5.10@2592.58,1783.25
REF_CLK: HDR_B1.4 U4.AF14 | length 887.5
  Top Layer w5: U4.AF14@1543.31,984.25 1543.31,952.76 1562.99,933.07 1562.99,779.53 1582.68,759.84 1582.68,740.16 v1(1559.06,716.54)
  MidLayer1 w5: v2(1153.54,688.98) 1153.54,665.35 1177.17,641.73 1511.81,641.73 1519.68,649.61 1519.68,673.23 1511.81,681.1 1511.81,700.79 1527.56,716.54 v1(1559.06,716.54)
  Bottom Layer w7.87: HDR_B1.4@1153.55,606.3 v2(1153.54,688.98)
RS232_CTS: HDR_T1.22 U4.B15 | length 901.3
  Top Layer w5: v2(1437.01,2665.35) 1437.01,2472.44 1582.68,2326.77 1582.68,2271.65 1570.87,2259.84 1570.87,2251.97 1570.87,2248.03 1606.3,2212.6 1606.3,2086.61 1562.99,2043.31 1562.99,2039.37 1562.99,2031.5 1562.99,1948.82 U4.B15@1582.68,1929.13
  Bottom Layer w7.87: HDR_T1.22@1437.01,2606.3 v2(1437.01,2665.35)
RS232_RTS: HDR_T1.18 U4.B11 | length 885
  Top Layer w5: v2(1374.01,2665.35) 1374.01,2472.44 1480.31,2366.14 1480.31,2271.65 1488.19,2263.78 1488.19,2248.03 1405.51,2165.35 1405.51,2043.31 1405.51,2031.5 1405.51,1948.82 U4.B11@1425.2,1929.13
  Bottom Layer w7.87: HDR_T1.18@1374.02,2606.3 v2(1374.01,2665.35)
RS232_RX: HDR_T1.24 U4.B16 | length 922.4
  Top Layer w5: v2(1468.5,2688.98) 1468.5,2464.57 1606.3,2326.77 1606.3,2271.65 1618.11,2259.84 1618.11,2251.97 1618.11,2208.66 1641.73,2185.04 1641.73,2039.37 1641.73,2031.5 1641.73,1948.82 U4.B16@1622.05,1929.13
  Bottom Layer w7.87: HDR_T1.24@1468.5,2606.3 v2(1468.5,2688.98)
RS232_TX: HDR_T1.20 U4.A14 | length 902.6
  Top Layer w5: v2(1405.51,2688.98) 1405.51,2464.57 1543.31,2326.77 1543.31,2271.65 1555.12,2259.84 1555.12,2244.09 1594.49,2204.72 1594.49,2098.43 1543.31,2047.24 1543.31,2039.37 1543.31,2031.5 U4.A14@1543.31,1968.5
  Bottom Layer w7.87: HDR_T1.20@1405.51,2606.3 v2(1405.51,2688.98)
SCL: HDR_B1.5 U4.Y11 | length 1129.5
  Top Layer w7.87: v1(1405.51,1200.78) U4.Y11@1425.2,1220.47
  MidLayer3 w5: v2(1185.04,279.53) 1185.04,629.92 1287.4,732.28 1338.58,732.28 1385.83,779.53 1385.83,909.45 1385.83,921.26 1385.83,1181.1 v1(1405.51,1200.78)
  Bottom Layer w7.87: v2(1185.04,279.53) HDR_B1.5@1185.04,338.58
SDA: HDR_B1.3 U4.AA10 | length 1056.8
  Top Layer w7.87: v1(1366.14,1161.41) U4.AA10@1385.83,1181.1
  MidLayer3 w5: v2(1153.54,279.53) 1153.54,661.42 1346.46,854.33 1346.46,909.45 1346.46,921.26 1346.46,1141.73 v1(1366.14,1161.41)
  Bottom Layer w7.87: v2(1153.54,279.53) HDR_B1.3@1153.55,338.58
SLEEP_N: HDR_T1.93
SPI_CLK: HDR_T1.46 U4.F14 | length 1091.4
  Top Layer w7.87: U4.F14@1543.31,1771.65 v1(1562.99,1791.34)
  MidLayer2 w5: v1(1562.99,1791.34) 1543.31,1811.02 1543.31,2031.49 1543.31,2039.37 1543.31,2047.24 1740.16,2244.09 1740.16,2263.78 1728.35,2275.59 1728.35,2295.28 1814.96,2381.89 v2(1814.96,2665.35)
  Bottom Layer w7.87: HDR_T1.46@1814.96,2606.3 v2(1814.96,2665.35)
SPI_DIN: HDR_T1.44 U4.F13 | length 1206.1
  Top Layer w7.87: v1(1484.25,1791.34) U4.F13@1503.94,1771.65
  MidLayer2 w5: v1(1484.25,1791.34) 1464.57,1811.02 1464.57,1866.14 1464.57,1960.64 1484.25,1980.32 1484.25,2031.49 1484.25,2039.37 1484.25,2208.66 1507.87,2232.28 1606.3,2232.28 1646.13,2272.11 1649.61,2275.59 1649.61,2318.9 1704.72,2374.02 1704.72,2582.68 1783.46,2661.42 v2(1783.46,2688.98)
  Bottom Layer w7.87: HDR_T1.44@1783.47,2606.3 v2(1783.46,2688.98)
SPI_DOUT: HDR_T1.50 U4.F16 | length 1093.1
  Top Layer w7.87: U4.F16@1622.05,1771.65 v1(1641.73,1791.34)
  MidLayer2 w5: v1(1641.73,1791.34) 1622.05,1811.02 1622.05,1866.14 1622.05,1968.51 1645.67,1992.13 1645.67,2031.49 1645.67,2039.37 1645.67,2110.24 1767.72,2232.28 1787.4,2232.28 1803.15,2248.03 1803.15,2263.78 1795.28,2271.65 1795.28,2291.34 1877.95,2374.01 v2(1877.95,2665.35)
  Bottom Layer w7.87: HDR_T1.50@1877.95,2606.3 v2(1877.95,2665.35)
SPI_MODE: HDR_T1.52 U4.F17 | length 1135.8
  Top Layer w7.87: U4.F17@1661.42,1771.65 v1(1681.1,1791.34)
  MidLayer2 w5: v1(1681.1,1791.34) 1661.42,1811.02 1661.42,2031.49 1661.42,2039.37 1661.42,2107.28 1774.61,2220.47 1803.15,2220.47 1822.83,2240.16 1822.83,2259.84 1909.45,2346.46 v2(1909.45,2688.98)
  Bottom Layer w7.87: HDR_T1.52@1909.45,2606.3 v2(1909.45,2688.98)
SPI_SEL: HDR_T1.48 U4.F15 | length 1125.6
  Top Layer w7.87: U4.F15@1582.68,1771.65 v1(1602.36,1791.34)
  MidLayer2 w5: v1(1602.36,1791.34) 1582.68,1811.02 1582.68,2031.5 1582.62,2039.37 1582.62,2066.87 1763.78,2248.03 1763.78,2263.78 1775.59,2275.59 1775.59,2287.4 1846.46,2358.27 v2(1846.46,2688.98)
  Bottom Layer w7.87: HDR_T1.48@1846.46,2606.3 v2(1846.46,2688.98)
SRAM1_A0: U4.AC18 U9.1 | length 1163.8
  Top Layer w7.87: U4.AC18@1700.79,1102.36 v1(1720.47,1082.67)
  MidLayer1 w5: v1(1720.47,1082.67) 1740.16,1062.99 1740.16,1007.87 1720.47,988.19 1720.47,921.26 1720.47,909.45 1720.47,870.08 1755.91,834.65 1771.65,818.9 1779.53,818.9 1870.08,728.35 v1(2523.62,728.35)
  Bottom Layer w5: U9.1@2478.44,728.34 v1(2523.62,728.35)
SRAM1_A1: U4.AC19 U9.2 | length 1160
  Top Layer w7.87: U4.AC19@1740.16,1102.36 v1(1759.84,1082.67)
  MidLayer1 w5: v1(1759.84,1082.67) 1779.53,1062.99 1779.53,937.01 1763.78,921.26 1763.78,909.45 1763.78,858.27 1775.59,846.46 1787.4,846.46 1874.02,759.84 v1(2547.24,759.84)
  Bottom Layer w5: U9.2@2478.44,759.83 v1(2547.24,759.84)
SRAM1_A2: U4.AD21 U9.3 | length 997.3
  Top Layer w7.87: U4.AD21@1818.9,1062.99 v1(1838.58,1043.3)
  MidLayer1 w5: v1(1838.58,1043.3) 1838.58,1035.44 1814.96,1011.81 1814.96,921.26 1814.96,909.45 1814.96,870.08 1838.58,846.46 1901.57,846.46 1956.69,791.34 v1(2523.62,791.34)
  Bottom Layer w5: U9.3@2478.44,791.33 v1(2523.62,791.34)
